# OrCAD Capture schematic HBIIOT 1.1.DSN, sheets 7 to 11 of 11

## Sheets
7 EXP CN: size C; title: BOOT, EXP; rev: 2.4.0
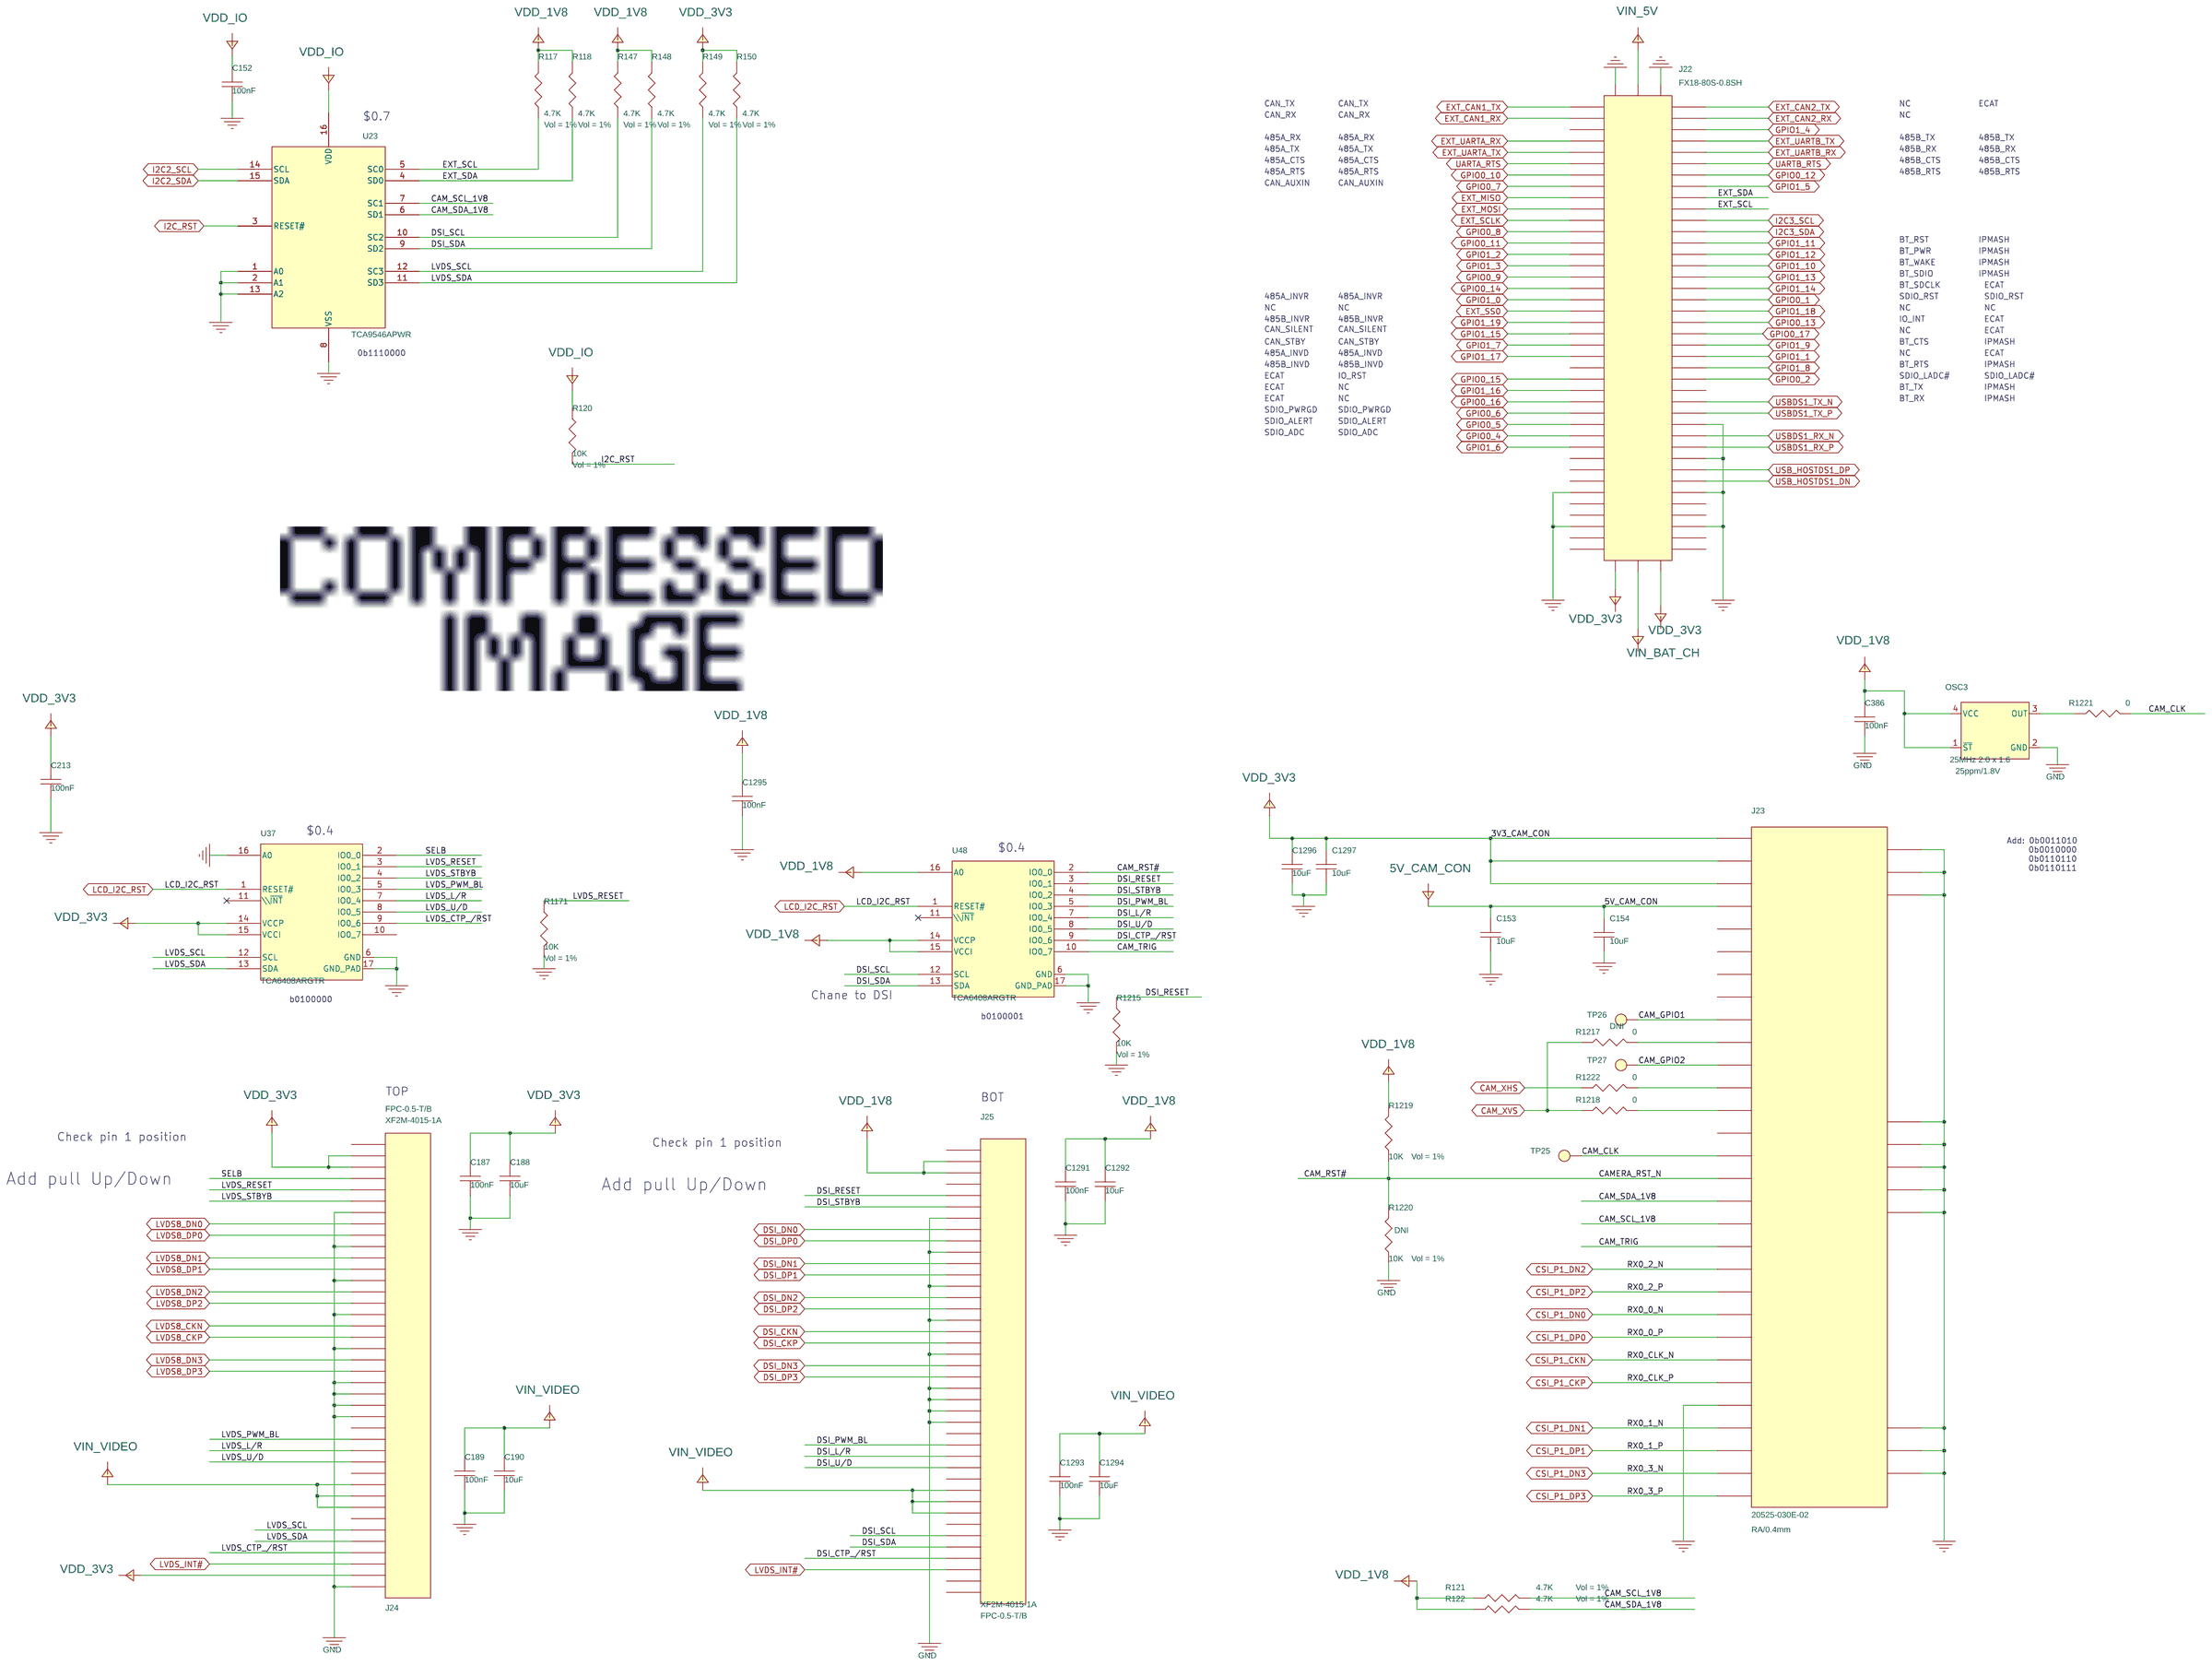
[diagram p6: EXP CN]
8 06 Sensors: size B
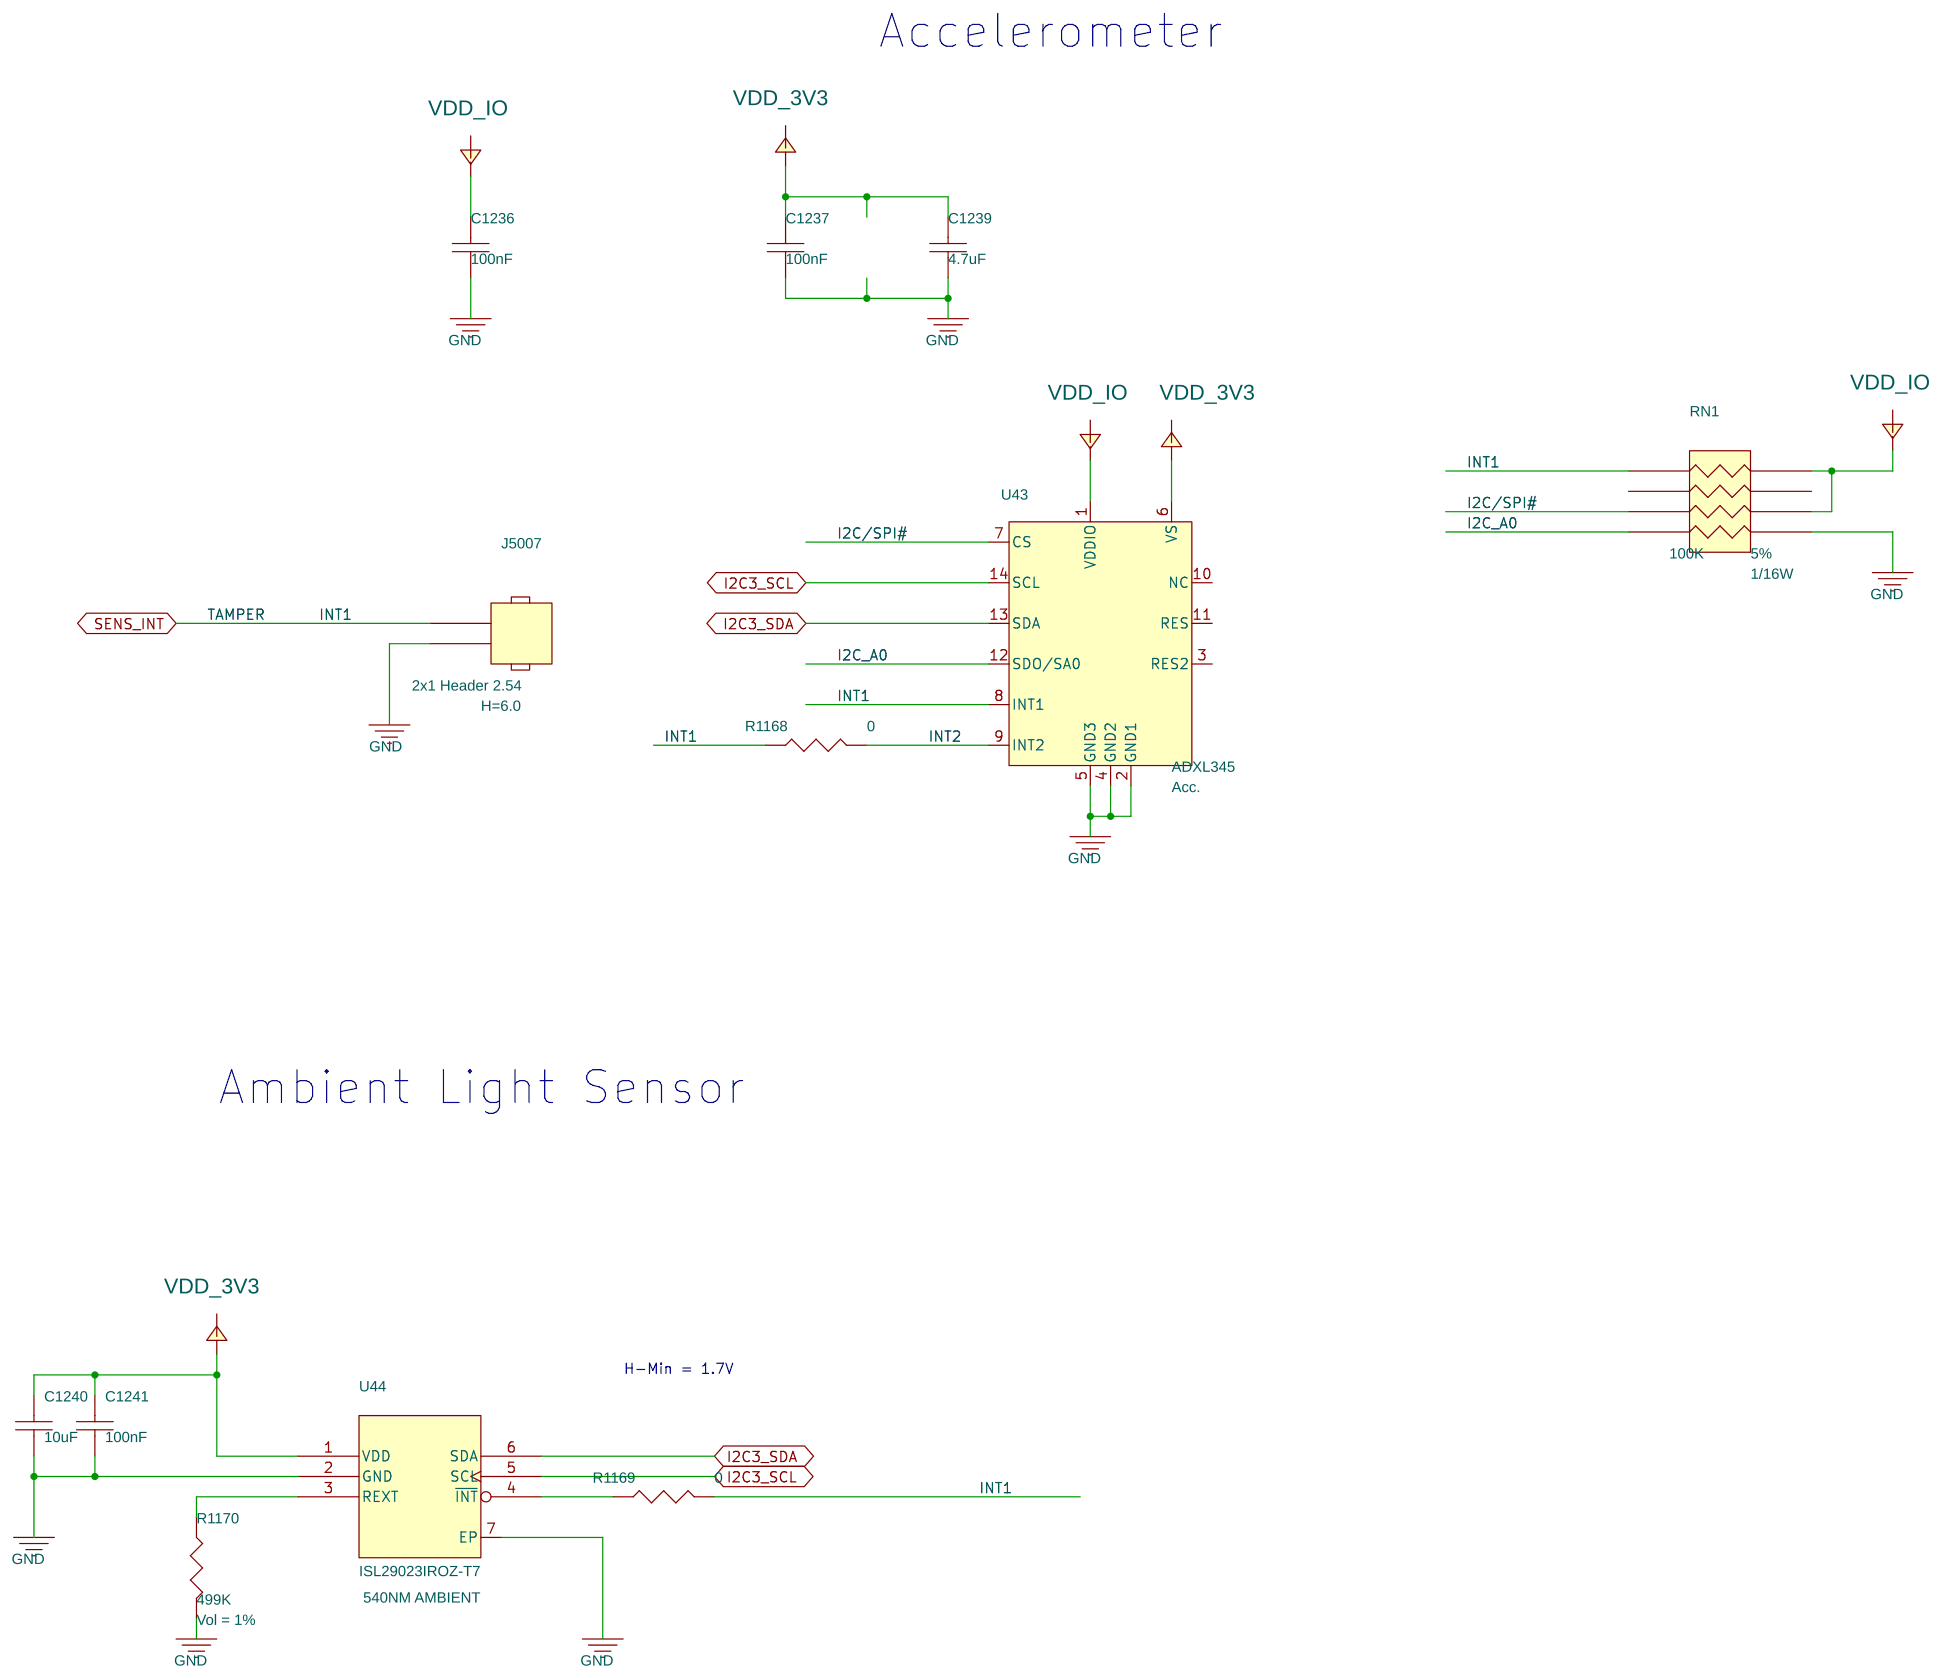
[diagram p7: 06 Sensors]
9 03 Battery Charger: size B; rev: 1.3
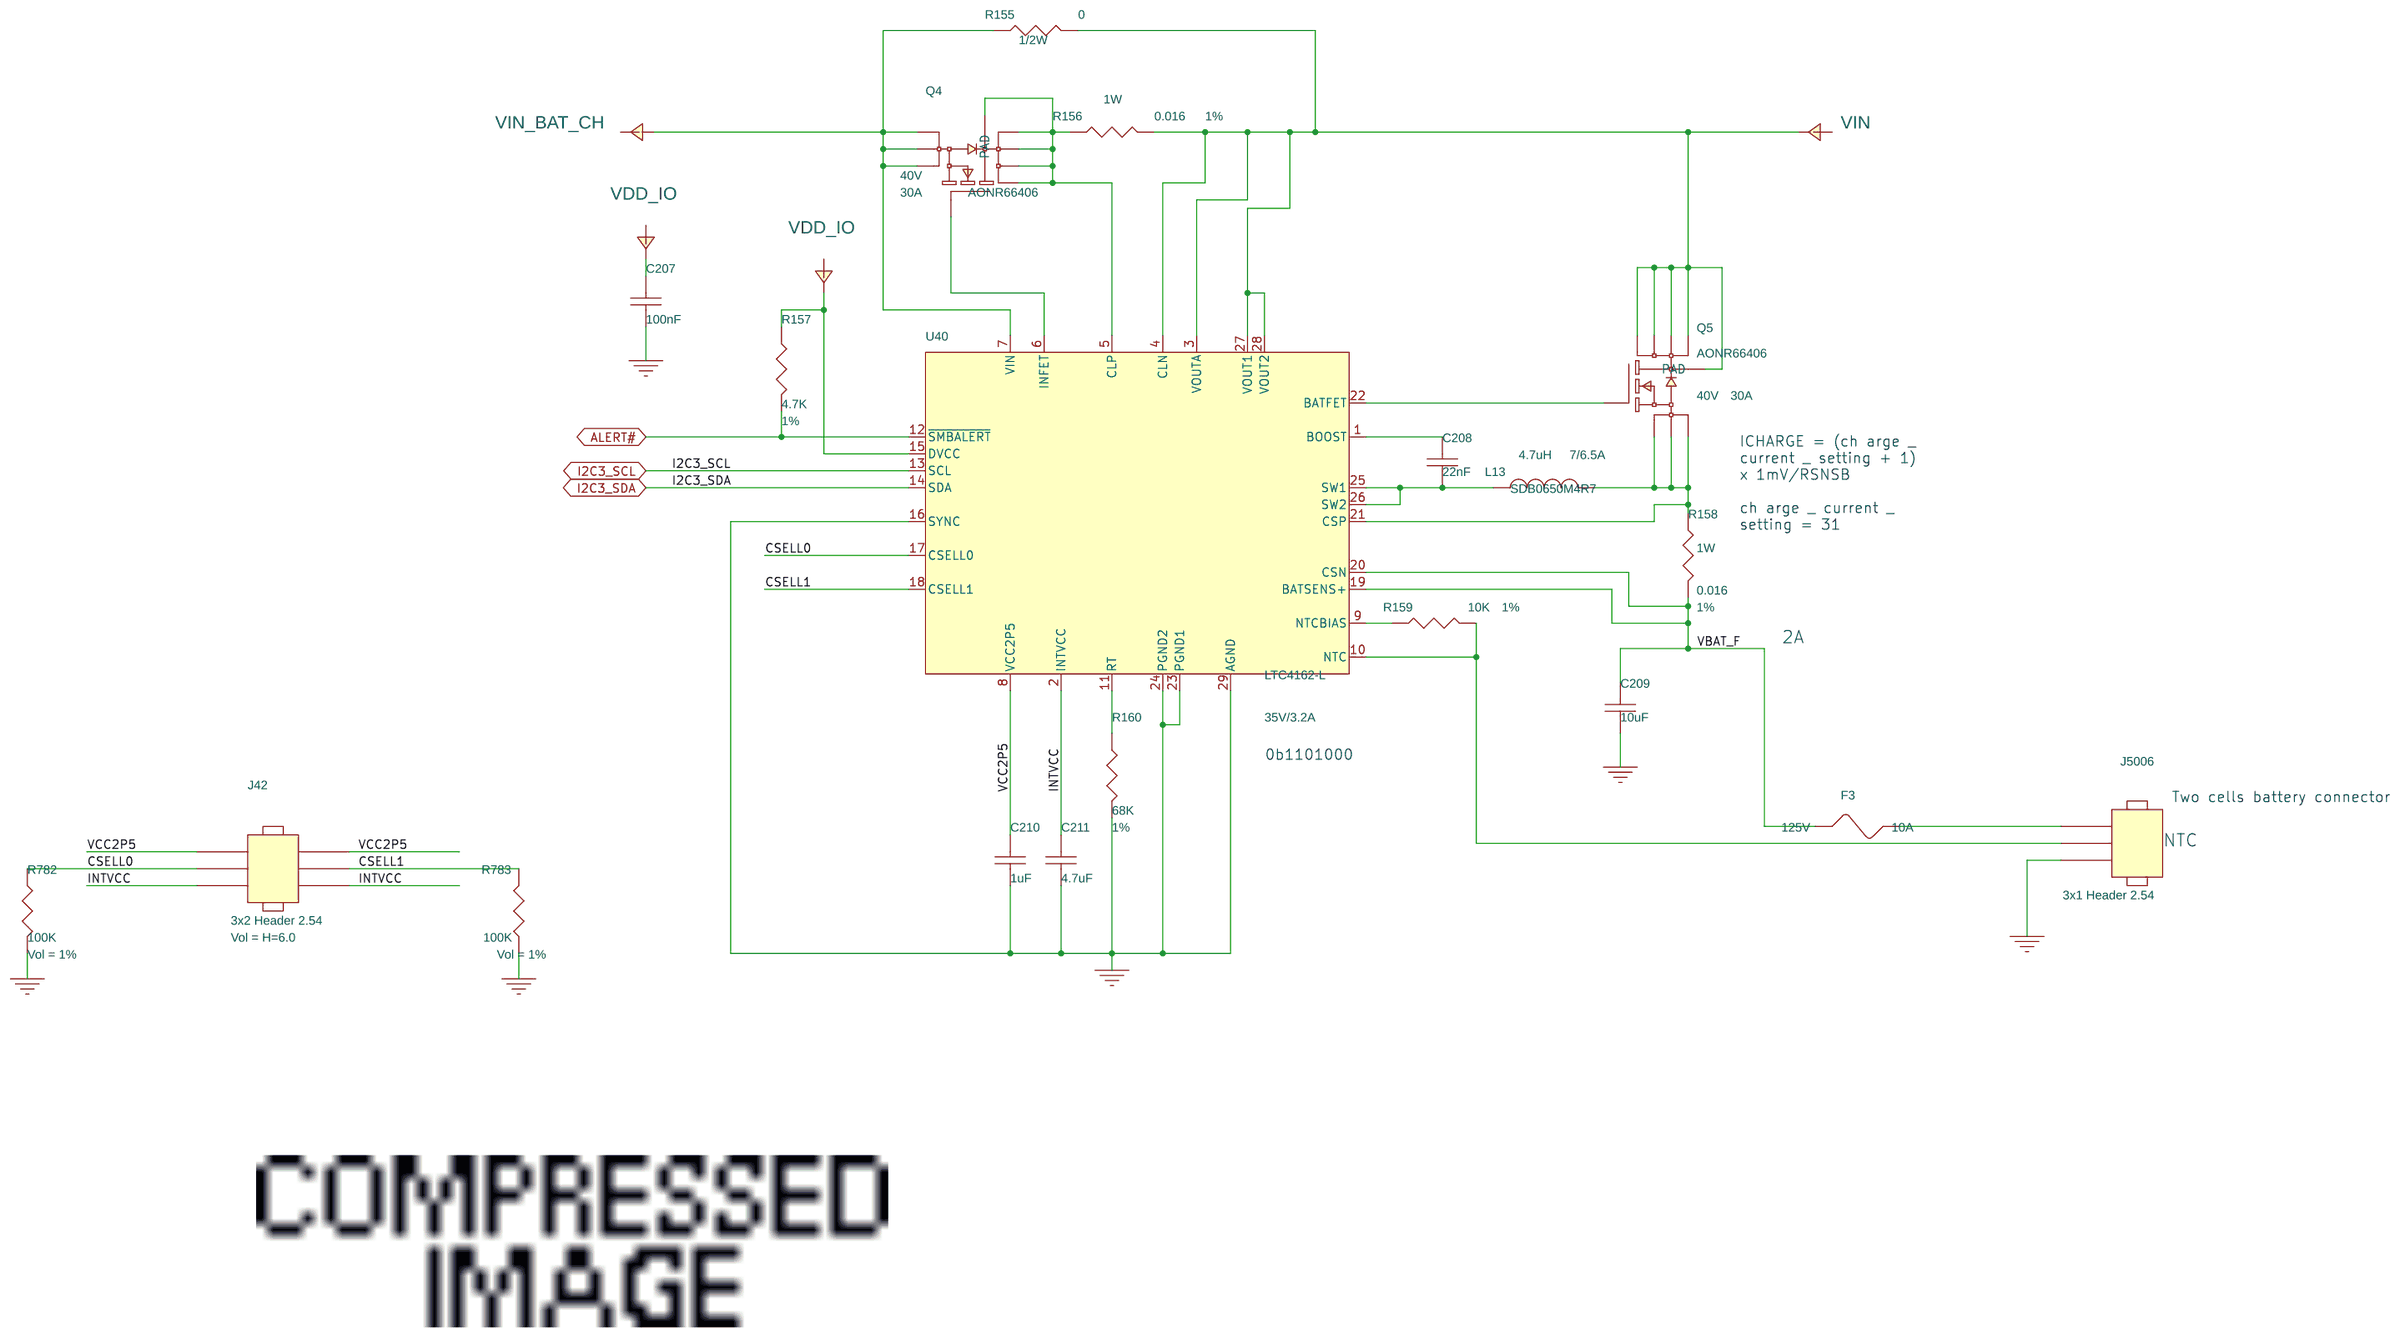
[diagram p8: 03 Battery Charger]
10 History: title: HISTORY
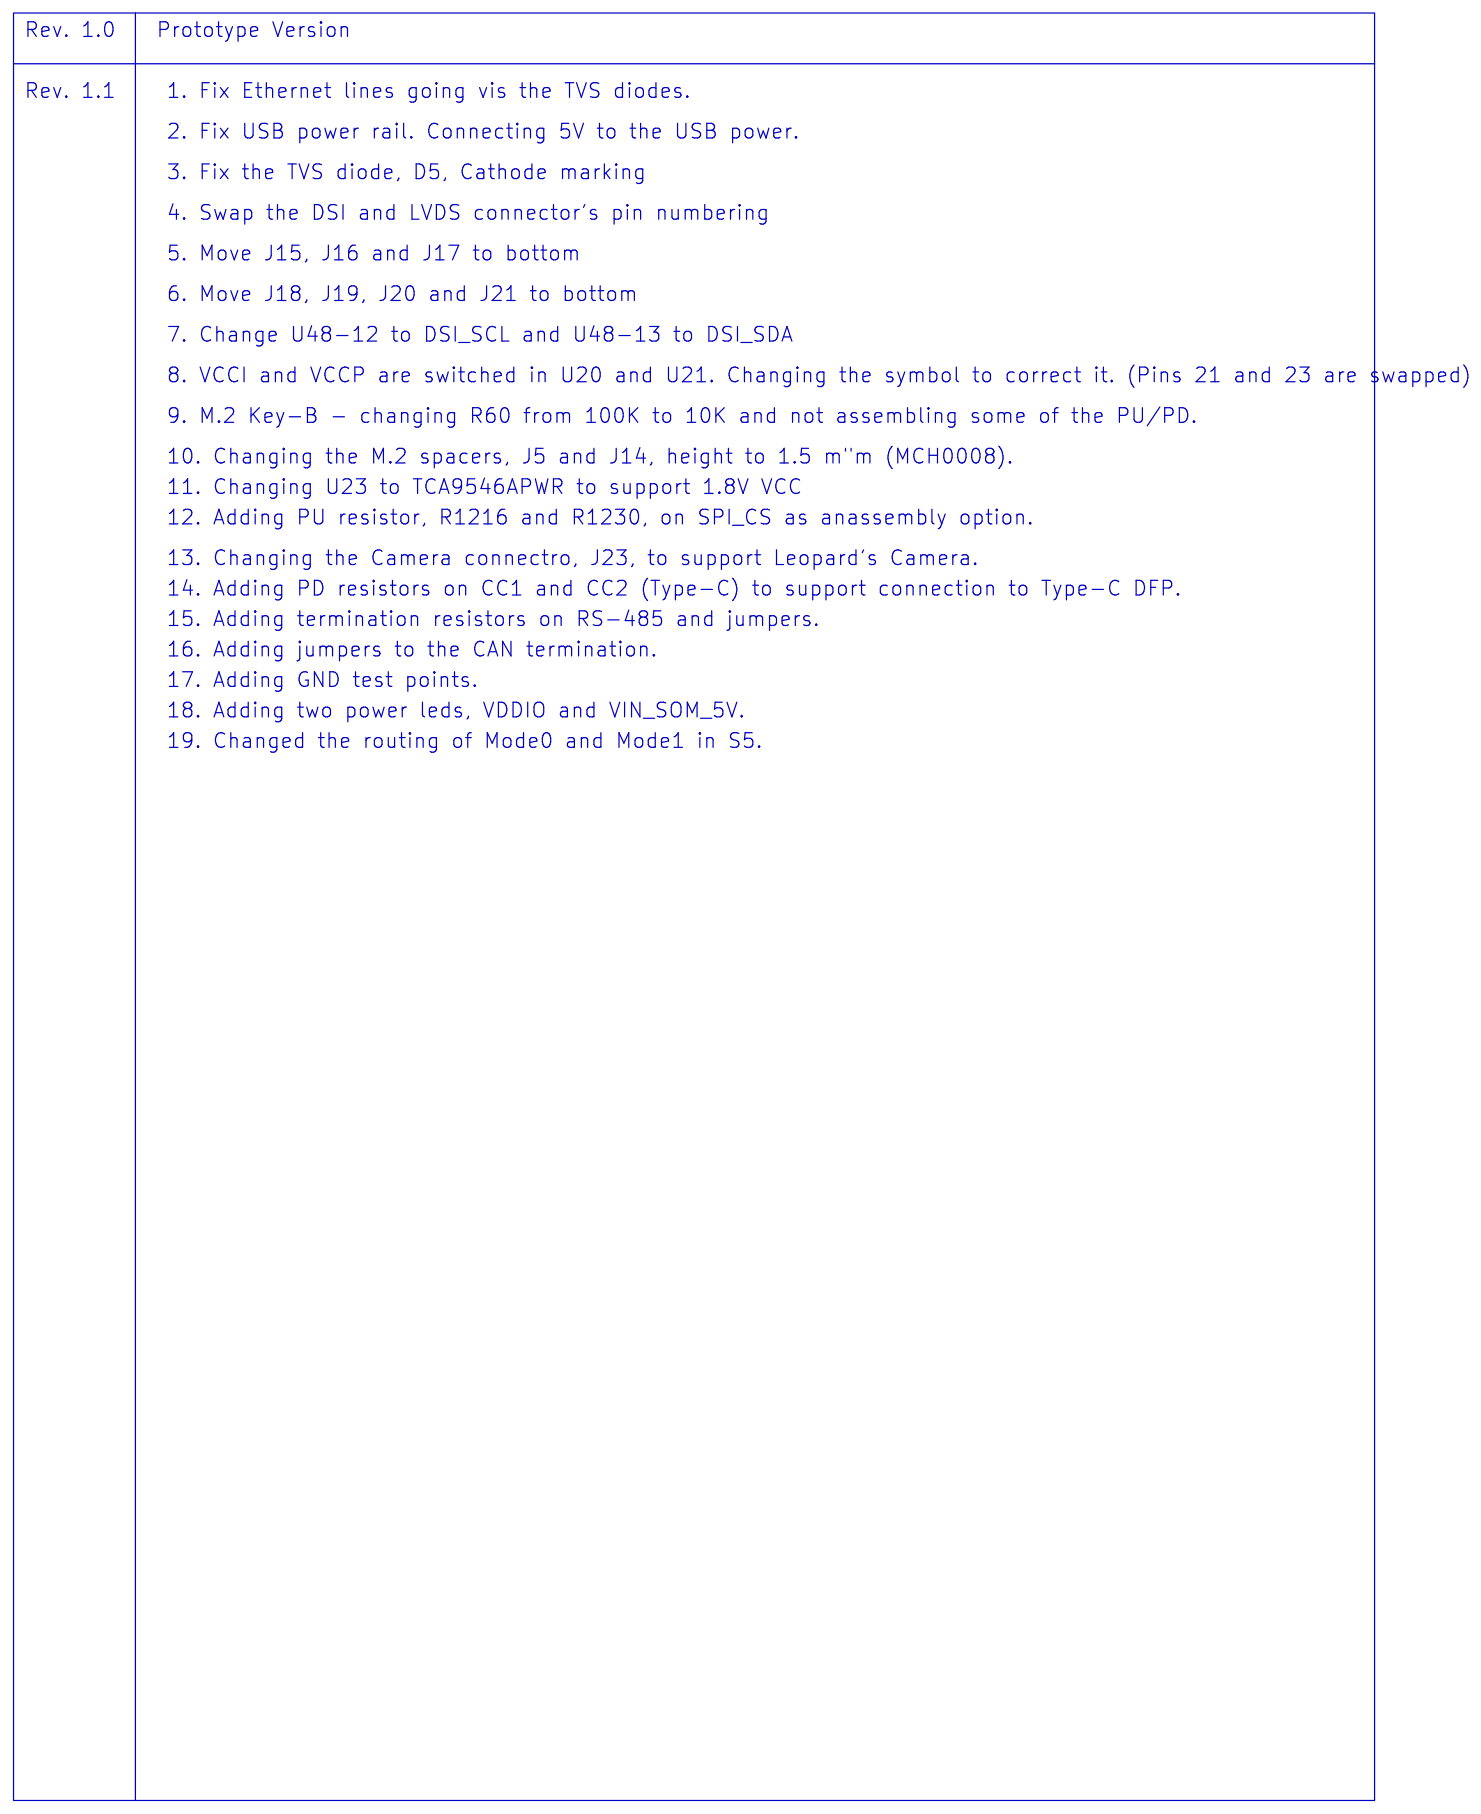
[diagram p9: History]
11 10 RS422/85/232: size C; title: RS422; rev: 1.0
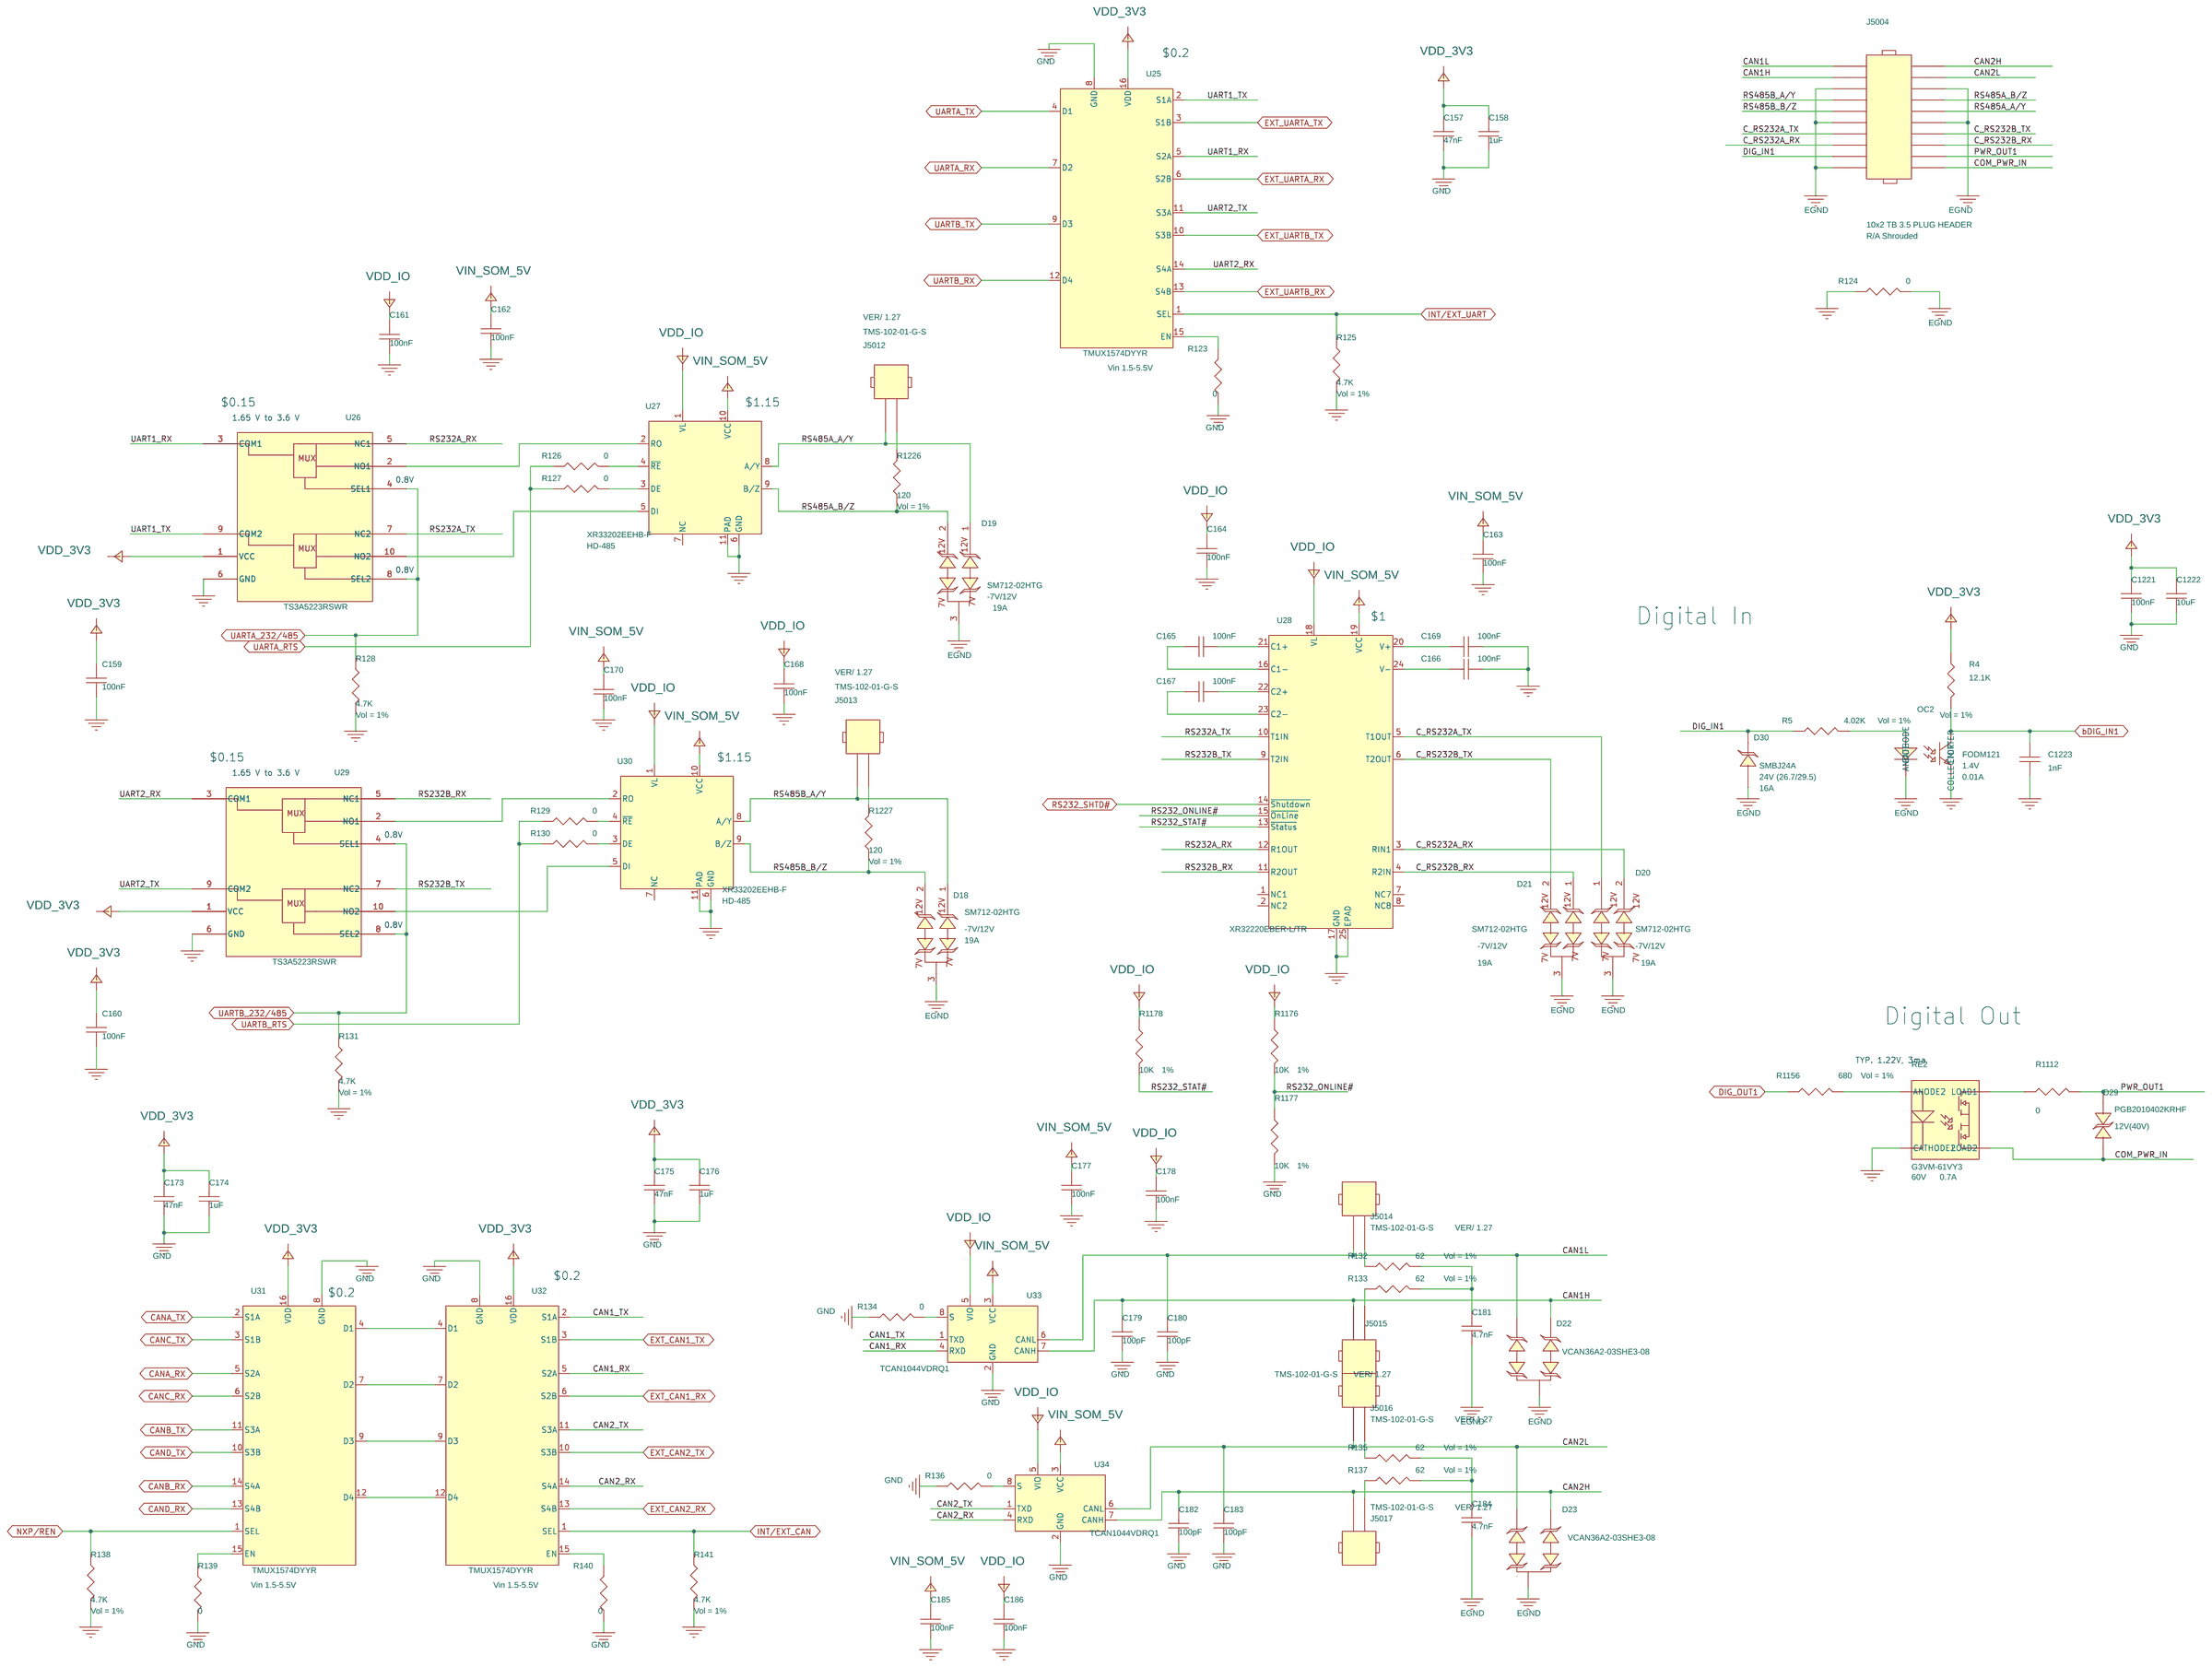
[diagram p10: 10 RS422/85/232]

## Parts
sheet 03 Battery Charger
C207  100nF  [C0402]
C208  22nF  [C0402]
C209  10uF  [C0603]
C210  1uF  [C0402]
C211  4.7uF  [C0603]
F3  125V  [0154010.DR]
J42  3x2 Header 2.54  [CH81062V200]
J5006  3x1 Header 2.54  [CH31032V200-NH]
L13  SDB0650M4R7  [SDB0650M4R7]
Q4  AONR66406  [AONR66406]
Q5  AONR66406  [AONR66406]
R155  0  [R0603]
R156  0.016  [R2512]
R157  4.7K  [R0402]
R158  0.016  [R2512]
R159  10K  [R0402]
R160  68K  [R0402]
R782  100K  [R0402]
R783  100K  [R0402]
U40  LTC4162-L  [LTC4162EUFD-LAD#TRPBF]
sheet 06 Sensors
C1236  100nF  [C0402]
C1237  100nF  [C0402]
C1239  4.7uF  [C0402]
C1240  10uF  [C0603]
C1241  100nF  [C0402]
J5007  2x1 Header 2.54  [CH31022V200-NH]
R1168  0  [R0402]
R1169  0  [R0402]
R1170  499K  [R0402]
RN1  100K  [RN0804]
U43  ADXL345  [ADXL345BCCZ-RL]
U44  ISL29023IROZ-T7  [ISL29023IROZ-T7]
sheet 10 RS422/85/232
C157  47nF  [C0402]
C158  1uF  [C0402]
C159  100nF  [C0402]
C160  100nF  [C0402]
C161  100nF  [C0402]
C162  100nF  [C0402]
C163  100nF  [C0402]
C164  100nF  [C0402]
C165  100nF  [C0402]
C166  100nF  [C0402]
C167  100nF  [C0402]
C168  100nF  [C0402]
C169  100nF  [C0402]
C170  100nF  [C0402]
C173  47nF  [C0402]
C174  1uF  [C0402]
C175  47nF  [C0402]
C176  1uF  [C0402]
C177  100nF  [C0402]
C178  100nF  [C0402]
C179  100pF  [C0402]
C180  100pF  [C0402]
C181  4.7nF  [C0402]
C182  100pF  [C0402]
C183  100pF  [C0402]
C184  4.7nF  [C0402]
C185  100nF  [C0402]
C186  100nF  [C0402]
C1221  100nF  [C0402]
C1222  10uF  [C0603]
C1223  1nF  [C0402]
D18  SM712-02HTG  [SM712-02HTG]
D19  SM712-02HTG  [SM712-02HTG]
D20  SM712-02HTG  [SM712-02HTG]
D21  SM712-02HTG  [SM712-02HTG]
D22  VCAN36A2-03SHE3-08  [VCAN36A2-03SHE3-08]
D23  VCAN36A2-03SHE3-08  [VCAN36A2-03SHE3-08]
D29  PGB2010402KRHF  [PGB2010402KRHF]
D30  SMBJ24A  [SMBJ24A]
J5004  10x2 TB 3.5 PLUG HEADER  [1787098]
J5012  TMS-102-01-G-S  [TMS-102-01-G-S]
J5013  TMS-102-01-G-S  [TMS-102-01-G-S]
J5014  TMS-102-01-G-S  [TMS-102-01-G-S]
J5015  TMS-102-01-G-S  [TMS-102-01-G-S]
J5016  TMS-102-01-G-S  [TMS-102-01-G-S]
J5017  TMS-102-01-G-S  [TMS-102-01-G-S]
OC2  FODM121  [FODM121]
R4  12.1K  [R0402]
R5  4.02K  [R0603]
R123  0  [R0402]
R124  0  [R0603]
R125  4.7K  [R0402]
R126  0  [R0402]
R127  0  [R0402]
R128  4.7K  [R0402]
R129  0  [R0402]
R130  0  [R0402]
R131  4.7K  [R0402]
R132  62  [R0603]
R133  62  [R0603]
R134  0  [R0402]
R135  62  [R0603]
R136  0  [R0402]
R137  62  [R0603]
R138  4.7K  [R0402]
R139  0  [R0402]
R140  0  [R0402]
R141  4.7K  [R0402]
R1112  0  [R0603]
R1156  680  [R0402]
R1176  10K  [R0402]
R1177  10K  [R0402]
R1178  10K  [R0402]
R1226  120  [R0402]
R1227  120  [R0402]
RE2  G3VM-61VY3  [G3VM-61VY3(TR05)]
U25  TMUX1574DYYR  [TMUX1574DYYR]
U26  TS3A5223RSWR  [TS3A5223RSWR]
U27  XR33202EEHB-F  [XR33202EEHB-F]
U28  XR32220EBER-L/TR  [XR32220EBER-L/TR]
U29  TS3A5223RSWR  [TS3A5223RSWR]
U30  XR33202EEHB-F  [XR33202EEHB-F]
U31  TMUX1574DYYR  [TMUX1574DYYR]
U32  TMUX1574DYYR  [TMUX1574DYYR]
U33  TCAN1044VDRQ1  [TCAN1044VDRQ1]
U34  TCAN1044VDRQ1  [TCAN1044VDRQ1]
sheet EXP CN
C152  100nF  [C0402]
C153  10uF  [C0402]
C154  10uF  [C0402]
C187  100nF  [C0402]
C188  10uF  [C0603]
C189  100nF  [C0402]
C190  10uF  [C0603]
C213  100nF  [C0402]
C386  100nF  [C0201]
C1291  100nF  [C0402]
C1292  10uF  [C0603]
C1293  100nF  [C0402]
C1294  10uF  [C0603]
C1295  100nF  [C0402]
C1296  10uF  [C0402]
C1297  10uF  [C0402]
J22  FX18-80S-0.8SH  [FX18-80S-0.8SH]
J23  20525-030E-02  [20525-030E-02]
J24  XF2M-4015-1A  [XF2M-4015-1A]
J25  XF2M-4015-1A  [XF2M-4015-1A]
OSC3  25MHz 2.0 x 1.6  [SIT1602BI-72-18E-25.000000]
R117  4.7K  [R0402]
R118  4.7K  [R0402]
R120  10K  [R0402]
R121  4.7K  [R0402]
R122  4.7K  [R0402]
R147  4.7K  [R0402]
R148  4.7K  [R0402]
R149  4.7K  [R0402]
R150  4.7K  [R0402]
R1171  10K  [R0402]
R1215  10K  [R0402]
R1217  0  [R0201]
R1218  0  [R0201]
R1219  10K  [R0402]
R1220  10K  [R0402]
R1221  0  [R0201]
R1222  0  [R0201]
TP25  R 20
TP26  R 20
TP27  R 20
U23  TCA9546APWR  [TCA9546APWR]
U37  TCA6408ARGTR  [TCA6408ARGTR]
U48  TCA6408ARGTR  [TCA6408ARGTR]

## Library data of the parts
C207 = CAP_NP1: CAP CER 0.1uF ±10% 10V X7R 0402; Category: Capacitors (Size: 0402); Digikey P/N: 1276-1002-2-ND; Manufacturer: Samsung Electro-Mechanics; Part Num#: CL05B104KP5NNNC; Rating: 10V; SolidRun P/N: CA20001; Vol: 10%
C208 = CAP_NP1: CAP CER 0.022UF 25V X7R 0402; Category: Capacitors (Size: 0402); Digikey P/N: 1276-1537-2-ND; Manufacturer: Samsung Electro-Mechanics; Part Num#: CL05B223KA5NNNC; Rating: 25V; SolidRun P/N: CA20822; Vol: 10%
C209 = CAP_NP1: CAP CER 10uF ±10% 16V X5R 0603; Digikey P/N: 490-10728-2-ND; Manufacturer: Murata Electronics North America; Part Num#: GRM188R61C106KAALD; Rating: 16V; SolidRun P/N: CA30014; Vol: 10%
C210 = CAP_NP1: CAP CER 1UF 10V X5R 0402; Category: Capacitors (Size: 0402); Digikey P/N: 1276-1076-1-ND; Manufacturer: Samsung Electro-Mechanics; Part Num#: CL05A105KP5NNNC; Rating: 10V; SolidRun P/N: CA20005; Vol: 10%
C211 = CAP_NP1: CAP CER 4.7uF ±10% 10V X5R 0603; Category: Capacitors (Size: 0603); Digikey P/N: 311-1455-1-ND; Manufacturer: YAGEO; Part Num#: CC0603KRX5R6BB475; Rating: 10V; SolidRun P/N: CA30017; Vol: 10%
F3 = FUSE1: FUSE BRD MNT 10A 125VAC/VDC SMD; Category: Fuse; Digikey P/N: F1251TR-ND; Manufacturer: Littelfuse Inc.; Rating: 10A; SolidRun P/N: FS00024; Datasheet: http://www.littelfuse.com/~/media/electronics/datasheets/fuses/littelfuse_fuse_154_154t_154l_154tl_datasheet.pdf.pdf
J42 = J-HEADER-3x2: 100 mil head 3 x 2 2.54mm H=6.0; Manufacturer: cvilux; SolidRun P/N: CO00507; Vol: H=6.0; Datasheet: https://www.cvilux.com/uploads/catalog/p285%20CH81-1.pdf
J5006 = J-HEADER-3x1: CH31 Series 2.54mm(.100") Single Row Pin Headers- 3 x 1 V TH; Category: CON-HEADER; Manufacturer: cvilux; SolidRun P/N: CO00509; VOL: H=6.0; Datasheet: https://www.cvilux.com/uploads/catalog/p283%20CH31.pdf
L13 = INDUCTOR1: IND 4.7uH 6.8 x 7.6 x 5 30.3mOhm 7/6.5A; Category: COILS-IND; Manufacturer: VIKING; Rating: 7/6.5A; SolidRun P/N: IN00045; Vol: 4.7uH; Datasheet: https://www.viking.com.tw/Templates/att/SDB_REV_B5-160912.pdf?lng=en
Q4 Q5 = MOSFET_N_DFN: 40V N-Channel AlphaSGT 30A; Category: TR-MOSFET-N; Digikey P/N: AONR66406-ND; Manufacturer: Alpha & Omega Semiconductor Inc; Rating: 30A; SolidRun P/N: TR00018; Vol: 40V; Datasheet: http://aosmd.com/res/data_sheets/AONR66406.pdf
R155 = RES1: RES SMD 0 OHM JUMPER 1/2W 0603; Category: Resistors (Size: 0603); Digikey P/N: 36-5110CT-ND; Manufacturer: Keystone Electronics; Part Num#: 5110; Rating: 1/2W; SolidRun P/N: RE30017
R156 R158 = RES1: 16 mOhms ±1% 1W Chip Resistor 2512 (6432 Metric) Current Sense Metal Element; Category: Resistors (Size: 2512); Digikey P/N: P16MTR-ND; Manufacturer: Panasonic Electronic Components; Part Num#: ERJ-M1WSF16MU; Rating: 1W; SolidRun P/N: RE70006; Vol: 1%
R117 R118 R121 R122 R147-R150 R157 = RES1: RES SMD 4.7K OHM 1% 1/16W 0402; Category: Resistors (Size: 0402); Digikey P/N: 311-4.7KLRCT-ND; Manufacturer: YAGEO; Part Num#: RC0402FR-074K7L; Rating: 1/16W; SolidRun P/N: RE20497; Vol: 1%
R159 = RES1: RES SMD 10K OHM 1% 1/16W 0402; Category: Resistors (Size: 0402); Digikey P/N: 311-10.0KLRCT-ND; Manufacturer: YAGEO; Part Num#: RC0402FR-0710KL; Rating: 1/16W; SolidRun P/N: RE20013; Vol: 1%
R160 = RES1: RES SMD 68K OHM 1% 1/16W 0402; Category: Resistors (Size: 0402); Digikey P/N: 311-68.0KLRCT-ND; Manufacturer: YAGEO; Part Num#: RC0402FR-0768KL; Rating: 1/16W; SolidRun P/N: RE20104; Vol: 1%
R782 R783 = RES1: RES SMD 100K OHM 1% 1/16W 0402; Digikey P/N: 311-100KLRCT-ND; Manufacturer: YAGEO; Part Num#: RC0402FR-07100KL; Rating: 1/16W; SolidRun P/N: RE20482; Vol: 1%
U40 = IC-LTC4162-x: Battery Charger 35V/3.2A MULTI-CELL LITHIUM-ION; Category: IC-PWR-BAT; Digikey P/N: LTC4162EUFD-LAD#TRPBF-ND; Manufacturer: Linear Technology/Analog Devices; Rating: 35V/3.2A; SolidRun P/N: IC01252; VOL: Li-Ion; Datasheet: http://www.analog.com/media/en/technical-documentation/data-sheets/LTC4162-L.pdf
C161-C170 C177 C178 C185 C186 C1236 C1237 C1241 = CAP_NP1: CAP CER 0.1uF ±10% 10V X7R 0402; Digikey P/N: 1276-1002-2-ND; Manufacturer: Samsung Electro-Mechanics; Part Num#: CL05B104KP5NNNC; Rating: 10V; SolidRun P/N: CA20001; Vol: 10%
C1239 = CAP_NP1: CAP CER 4.7uF ±20% 6.3V X5R 0402; Digikey P/N: 490-5408-1-ND; Manufacturer: Murata Electronics North America; Part Num#: GRM155R60J475ME87D; Rating: 6.3V; SolidRun P/N: CA20800; Vol: 20%
C1240 = CAP_NP1: CAP CER 10uF ±10% 6.3V X5R 0603; Digikey P/N: 1276-1038-1-ND; Manufacturer: Samsung Electro-Mechanics; Part Num#: CL10A106KQ8NNNC; Rating: 6.3V; SolidRun P/N: CA30001; Vol: 10%
J5007 = J-HEADER_2x1: Two pin header - CH31022V200-NH; Manufacturer: CVILUX; SolidRun P/N: CO00049; Vol: H=6.0; Datasheet: https://www.cvilux.com/uploads/catalog/p283%20CH31.pdf
R123 R126 R127 R129 R130 R134 R136 R139 R140 R1168 R1169 = RES1: RES SMD 0 OHM JUMPER 1/16W 0402; Digikey P/N: 311-0.0JRCT-ND; Manufacturer: YAGEO; Part Num#: RC0402JR-070RL; Rating: 1/16W; SolidRun P/N: RE20009
R1170 = RES1: RES SMD 499K OHM 1% 1/16W 0402; Category: Resistors (Size: 0402); Digikey P/N: 311-499KLRTR-ND; Manufacturer: YAGEO; Part Num#: RC0402FR-07499KL; Rating: 1/16W; SolidRun P/N: RE20519; Vol: 1%
RN1 = RES-4: Resistor Network 4-RES 100K Ohm 5% 1/16W 0804; Digikey P/N: YC124J-100KCT-ND; Manufacturer: YAGEO; Part Num#: YC124-JR-07100KL; Rating: 1/16W; SolidRun P/N: RN00037; Vol: 5%
U43 = IC-ADX345: Accelerometer X, Y, Z Axis ±2g, 4g, 8g, 16g 0.05Hz ~ 1.6kHz 14-LGA (3x5); Digikey P/N: ADXL345BCCZ-RLTR-ND; Manufacturer: Analog Devices Inc.; SolidRun P/N: IC01454; Vol: Acc.; Datasheet: https://www.analog.com/media/en/technical-documentation/data-sheets/ADXL345.pdf
U44 = IC-ISL29023: SENSOR OPT 540NM AMBIENT 6ODFN; Digikey P/N: ISL29023IROZ-T7DKR-ND; Manufacturer: Renesas Electronics America Inc; SolidRun P/N: IC01550; Vol: 540NM AMBIENT; Datasheet: https://media.digikey.com/pdf/Data%20Sheets/Renesas/isl29023_DS.pdf
C157 C173 C175 = CAP_NP1: CHIP CAP 47nF 6.3V 0402 X7R; Manufacturer: Samsung Electro-Mechanics; Part Num#: CL05B473MQQNNNE; Rating: 6.3V; SolidRun P/N: CA20012; Vol: 10%
C158 C174 C176 = CAP_NP1: CAP CER 1uF ±10% 6.3V X7R 0402; Digikey P/N: 1276-1513-1-ND; Manufacturer: Samsung Electro-Mechanics; Part Num#: CL05B105KQ5NQNC; Rating: 6.3V; SolidRun P/N: CA20132; Vol: 10%
C159 C160 = CAP_NP1: CAP CER 0.1uF ±10% 16V X7R 0402; Digikey P/N: 1276-1001-1-ND; Manufacturer: Samsung Electro-Mechanics; Part Num#: CL05B104KO5NNNC; Rating: 16V; SolidRun P/N: CA20013; Vol: 10%
C179 C180 C182 C183 = CAP_NP1: CAP CER 100pF ±5% 50V C0G/NP0 0402; Digikey P/N: CL05C101JB5NNND-ND; Manufacturer: Samsung Electro-Mechanics; Part Num#: CL05C101JB5NNND; Rating: 50V; SolidRun P/N: CA20120; Vol: 5%
C181 C184 = CAP_NP1: CAP CER 4.7nF ±10% 25V X7R 0402; Category: Capacitors (Size: 0402); Digikey P/N: 1276-1571-1-ND; Manufacturer: Samsung Electro-Mechanics; Part Num#: CL05B472KA5NNNC; Rating: 25V; SolidRun P/N: CA20802; Vol: 10%
C152 C187 C189 C213 C1221 C1291 C1293 C1295 = CAP_NP1: CAP CER 0.1uF ±10% 16V X7R 0402; Category: Capacitors (Size: 0402); Digikey P/N: 1276-1001-1-ND; Manufacturer: Samsung Electro-Mechanics; Part Num#: CL05B104KO5NNNC; Rating: 16V; SolidRun P/N: CA20013; Vol: 10%
C188 C190 C1222 C1292 C1294 = CAP_NP1: CAP CER 10uF ±10% 16V X5R 0603; Category: Capacitors (Size: 0603); Digikey P/N: 490-10728-2-ND; Manufacturer: Murata Electronics North America; Part Num#: GRM188R61C106KAALD; Rating: 16V; SolidRun P/N: CA30014; Vol: 10%
C1223 = CAP_NP1: CAP CER 1000pF ±10% 50V X7R 0402; Digikey P/N: 1276-1032-1-ND; Manufacturer: Samsung Electro-Mechanics; Part Num#: CL05B102KB5NNNC; Rating: 50V; SolidRun P/N: CA20008; Vol: 10%
D18-D21 = TVS-SM712-RS485: SM712 Series 600W Asymmetrical TVS Diode Array For RS-485; Digikey P/N: F6450TR-ND; Manufacturer: Littelfuse Inc.; Rating: 19A; SolidRun P/N: DI00265; Vol: -7V/12V; Datasheet: http://www.littelfuse.com/~/media/electronics/datasheets/tvs_diode_arrays/littelfuse_tvs_diode_array_sm712_datasheet.pdf.pdf
D22 D23 = D-ESDCAN05-TVS: 63V Clamp 2.4A (8/20µs) Ipp Tvs Diode Surface Mount SOT-23-3; Digikey P/N: 112-VCAN36A2-03SHE3-08TR-ND; Manufacturer: Vishay General Semiconductor - Diodes Division; Rating: 3A; SolidRun P/N: DI00314; Vol: 39/61V; Datasheet: https://www.vishay.com/docs/86182/vcan36a2-03s.pdf
D29 = TVS-BI: 40V (Typ) Clamp - Ipp Tvs Diode Surface Mount 0402; Digikey P/N: F3268TR-ND; Manufacturer: Littelfuse Inc.; SolidRun P/N: DI00305; Vol: 12V(40V); Datasheet: https://www.littelfuse.com/media?resourcetype=datasheets&itemid=1cf7e392-caf0-4fab-b036-960455903eff&filename=littelfuse-pulseguard-pgb2-0402-datasheet
D30 = TVS-UNI-OLD: TVS Diodes - TVS DIODE 24V 38.9V DO214AA; Digikey P/N: SMBJ24AR5GTR-ND; Manufacturer: Taiwan Semiconductor Corporation; Rating: 16A; SolidRun P/N: DI00218; Vol: 24V (26.7/29.5); Datasheet: http://www.taiwansemi.com/products/datasheet/SMBJ%20SERIES_O1701.pdf
J5004 = J-HEADER_10x2: 20 Position Terminal Block Header, Male Pins, Shrouded (4 Side) 0.138" (3.50mm) 90°, Right Angle Through Hole; Digikey P/N: 277-8743-ND; Manufacturer: Phoenix Contact; SolidRun P/N: CO00961; Vol: R/A Shrouded; Datasheet: https://mm.digikey.com/Volume0/opasdata/d220001/medias/docus/572/1787098.pdf
J5012-J5017 = J-HEADER_2x1: Connector Header Through Hole 2 position 0.050" (1.27mm); Digikey P/N: SAM12199-ND; Manufacturer: Samtec Inc.; Rating: H=5.84; SolidRun P/N: CO00974; Vol: VER/ 1.27; Datasheet: https://mm.digikey.com/Volume0/opasdata/d220001/medias/docus/6129/tms-1xx-xx-xx-x-xx-xxx-mkt.pdf
OC2 = OPTC-DC-4P: Optoisolator Transistor Output 3750Vrms 1 Channel 4-Mini-Flat; Digikey P/N: FODM121-ND; Manufacturer: ON Semiconductor; Rating: 0.01A; SolidRun P/N: IC01209; Vol: 1.4V; Datasheet: https://www.fairchildsemi.com/datasheets/FO/FODM121.pdf
R4 = RES1: RES SMD 12.1K OHM 1% 1/16W 0402; Digikey P/N: 311-12.1KLRCT-ND; Manufacturer: YAGEO; Part Num#: RC0402FR-0712K1L; Rating: 1/16W; SolidRun P/N: RE20433; Vol: 1%
R5 = RES1: RES SMD 4.02K OHM 1% 1/10W 0603; Digikey P/N: YAG5341TR-ND; Manufacturer: YAGEO; Part Num#: AC0603FR-074K02L; Rating: 1/10W; SolidRun P/N: RE30019; Vol: 1%
R124 = RES1: RES SMD 0 OHM JUMPER 1/2W 0603; Digikey P/N: 36-5110CT-ND; Manufacturer: Keystone Electronics; Part Num#: 5110; Rating: 1/2W; SolidRun P/N: RE30017
R125 R128 R131 R138 R141 = RES1: RES SMD 4.7K OHM 1% 1/16W 0402; Digikey P/N: 311-4.7KLRCT-ND; Manufacturer: YAGEO; Part Num#: RC0402FR-074K7L; Rating: 1/16W; SolidRun P/N: RE20497; Vol: 1%
R132 R133 R135 R137 = RES1: RES SMD 62 OHM 1% 1/4W 0603; Digikey P/N: RCS060362R0FKEA-ND; Manufacturer: Vishay Dale; Part Num#: RCS060362R0FKEA; Rating: 1/4W; SolidRun P/N: RE30025; Vol: 1%
R1112 = RES1: RES SMD 0 OHM JUMPER 1/10W 0603; Digikey P/N: 311-0.0GRCT-ND; Manufacturer: YAGEO; Part Num#: RC0603JR-070RL; Rating: 1/10W; SolidRun P/N: RE30006
R1156 = RES1: RES SMD 680 OHM 1% 1/16W 0402; Digikey P/N: 311-680LRCT-ND; Manufacturer: YAGEO; Part Num#: RC0402FR-07680RL; Rating: 1/16W; SolidRun P/N: RE20428; Vol: 1%
R1176-R1178 = RES1: RES SMD 10K OHM 1% 1/16W 0402; Category : Resistors (Size: 0402); Digikey P/N: 311-10.0KLRCT-ND; Manufacturer: YAGEO; Part Num#: RC0402FR-0710KL; Rating: 1/16W; SolidRun P/N: RE20013; Vol: 1%
R1226 R1227 = RES1: RES SMD 120 OHM 1% 1/16W 0402; Digikey P/N: 311-120LRCT-ND; Manufacturer: YAGEO; Part Num#: RC0402FR-07120RL; Rating: 1/16W; SolidRun P/N: RE20043; Vol: 1%
RE2 = RE-CPC1006N: SSR RELAY SPST-NO 700MA 0-60V; Digikey P/N: Z10318TR-ND; Manufacturer: Omron Electronics Inc-EMC Div; Rating: 0.7A; SolidRun P/N: IC01811; Vol: 60V; Datasheet: https://omronfs.omron.com/en_US/ecb/products/pdf/en-g3vm_61g_61vy1.pdf
U25 U31 U32 = IC-TMUX1574DYYR: 4 Circuit IC Switch 2:1 4.5Ohm 16-SOT-23-THIN; Digikey P/N: 296-TMUX1574DYYRTR-ND; Manufacturer: Texas Instruments; SolidRun P/N: IC01637; Vol: Vin 1.5-5.5V; Datasheet: https://www.ti.com/general/docs/suppproductinfo.tsp?distId=10&gotoUrl=https%3A%2F%2Fwww.ti.com%2Flit%2Fgpn%2Ftmux1574
U26 U29 = IC-TS3A5223RSWR: Dual analog switch - SPDT; Digikey P/N: 296-35687-2-ND; Manufacturer: Texas Instruments; SolidRun P/N: IC00220; Vol: SPDT; Datasheet: http://www.ti.com/lit/ds/symlink/ts3a5223.pdf
U27 U30 = IC-XR33202: 1/1 Transceiver Half RS422, RS485 10-DFN (3x3); Digikey P/N: 1016-2098-ND; Manufacturer: MaxLinear, Inc.; SolidRun P/N: IC01239; Vol: HD-485; Datasheet: https://www.exar.com/content/document.ashx?id=21713
U28 = IC-XR32220: 2/2 Transceiver Full RS232 24-QFN (4x4); Digikey P/N: 1016-XR32220EBER-L/TR-ND; Manufacturer: MaxLinear, Inc.; SolidRun P/N: IC01921; Datasheet: https://assets.maxlinear.com/web/documents/xr32220_ds_1e_080320.pdf
U33 U34 = IC-TCAN1044-SOIC8: 1/1 Transceiver - CAN 8-SOIC; Digikey P/N: 296-TCAN1044VDRQ1TR-ND; Manufacturer: Texas Instruments; SolidRun P/N: IC01667; Datasheet: https://www.ti.com/general/docs/suppproductinfo.tsp?distId=10&gotoUrl=https%3A%2F%2Fwww.ti.com%2Flit%2Fgpn%2Ftcan1044-q1
C153 C154 C1296 C1297 = CAP_NP1: CAP CER 10uF ±20% 6.3V X6S 0402; Digikey P/N: 490-13233-1-ND; Manufacturer: Murata Electronics North America; Part Num#: GRM155C80J106ME11D; Rating: 6.3V; SolidRun P/N: CA20131; Vol: 20%
C386 = CAP_NP1: CAP CER 0.1uF ±10% 10V X5R 0201; Digikey P/N: 587-2241-1-ND; Manufacturer: TAIYO YUDE; Part Num#: LMK063BJ104KP-F; Rating: 10V; SolidRun P/N: CA10004; Vol: 10%
J22 = J-FX18-80: 80 Position Connector Receptacle, Center Strip Contacts Surface Mount, Right Angle Gold; Digikey P/N: H12015-ND; Manufacturer: Hirose Electric Co Ltd; SolidRun P/N: CO00766; Vol: RCPT, R/A; Datasheet: https://www.hirose.com/product/document?clcode=CL0579-0005-3-00&productname=FX18-100P-0.8SH&series=FX18&documenttype=Catalog&lang=en&documentid=D31695_en
J23 = J-20525-030E-02C: 30 Position FPC Connector Contacts, Top 0.016" (0.40mm) Surface Mount, Right Angle; Digikey P/N: 3508-20525-030E-02TR-ND; Manufacturer: I-PEX; SolidRun P/N: CO00959; Vol: RA/0.4mm; Datasheet: https://www.i-pex.com/sites/default/files/downloads/pdf/CATALOG_CABLINE-CA_E.pdf
J24 J25 = J-FPC40: 40 Position FPC Connector Contacts, Top and Bottom 0.020" (0.50mm) Surface Mount, Right Angle; Digikey P/N: OR729TR-ND; Manufacturer: Omron Electronics Inc-EMC Div; SolidRun P/N: CO00681; Vol: FPC-0.5-T/B; Datasheet: https://media.digikey.com/pdf/Data%20Sheets/Omron%20PDFs/XF2M.pdf
OSC3 = OSC_4P_(3): 25 MHz XO (Standard) HCMOS, LVCMOS Oscillator 1.8V Enable/Disable 4-SMD, No Lead; Digikey P/N: 1473-SIT1602BI-72-18E-25.000000-ND; Manufacturer: SiTime; Rating: 25ppm/1.8V; SolidRun P/N: OC00059; Datasheet: https://www.sitime.com/datasheet/SiT1602
R120 R1171 R1215 R1219 = RES1: RES SMD 10K OHM 1% 1/16W 0402; Digikey P/N: 311-10.0KLRCT-ND; Manufacturer: YAGEO; Part Num#: RC0402FR-0710KL; Rating: 1/16W; SolidRun P/N: RE20013; Vol: 1%
R1217 = RES1: RES SMD 0 OHM JUMPER 1/20W 0201; ASSEMBLY: DNI; BOM_IGNORE: TRUE; Digikey P/N: RC0201JR-070RL; Manufacturer: YAGEO; Part Num#: RC0201JR-070RL; Rating: 1/20W; SolidRun P/N: RE10003
R1218 R1221 R1222 = RES1: RES SMD 0 OHM JUMPER 1/20W 0201; Digikey P/N: RC0201JR-070RL; Manufacturer: YAGEO; Part Num#: RC0201JR-070RL; Rating: 1/20W; SolidRun P/N: RE10003
R1220 = RES1: RES SMD 10K OHM 1% 1/16W 0402; ASSEMBLY: DNI; BOM_IGNORE: TRUE; Digikey P/N: 311-10.0KLRCT-ND; Manufacturer: YAGEO; Part Num#: RC0402FR-0710KL; Rating: 1/16W; SolidRun P/N: RE20013; Vol: 1%
TP25-TP27 = T_POINT_R: TEST POINT 20 mil - ultra miniature; ASSEMBLY: DNI; BOM_IGNORE: TRUE; Part Num#: N/A; SolidRun P/N: TP00003
U23 = IC-TCA9546APWR: IC BUS SWITCH 2 X 1:4 16TSSOP; Digikey P/N: 296-40578-2-ND; Manufacturer: Texas Instruments; SolidRun P/N: IC01984; Datasheet: https://www.ti.com/general/docs/suppproductinfo.tsp?distId=10&gotoUrl=https%3A%2F%2Fwww.ti.com%2Flit%2Fgpn%2Ftca9546a
U37 U48 = IC-TCA6408ARGTR: I/O Expander 8 I²C, SMBus 400kHz 16-QFN (3x3); Digikey P/N: 296-24825-2-ND; Manufacturer: Texas Instruments; SolidRun P/N: IC01238; Datasheet: http://www.ti.com/lit/ds/symlink/tca6408a.pdf

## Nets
GND: C152.2 C153.2 C154.2 C157.2 C158.2 C159.2 C160.2 C161.2 C162.2 C163.2 C164.2 C166.2 C168.2 C169.2 C170.2 C173.2 C174.2 C175.2 C176.2 C177.2 C178.2 C179.2 C180.2 C182.2 C183.2 C185.2 C186.2 C187.2 C188.2 C189.2 C190.2 C207.2 C209.2 C210.2 C211.2 C213.2 C386.2 C1221.2 C1222.2 C1223.2 C1236.2 C1237.2 C1239.2 C1240.2 C1241.2 C1291.2 C1292.2 C1293.2 C1294.2 C1295.2 C1296.2 C1297.2 J22.35 J22.38 J22.69 J22.72 J22.75 J22.78 J22.P1 J22.P3 J23.26 J23.31 J23.32 J23.33 J23.34 J23.35 J23.36 J23.37 J23.38 J23.39 J23.40 J23.41 J24.1 J24.16 J24.17 J24.18 J24.19 J24.22 J24.25 J24.28 J24.31 J24.34 J25.7 J25.10 J25.13 J25.16 J25.19 J25.22 J25.23 J25.24 J25.25 J5006.3 J5007.2 OC2.3(EMITTER) OSC3.2(GND) R123.2 R124.1 R125.2 R128.2 R131.2 R134.1 R136.1 R138.2 R139.2 R140.2 R141.2 R160.2 R782.2 R783.2 R1170.2 R1171.2 R1177.2 R1215.2 R1220.2 RE2.2(CATHODE2) RN1.5 U23.1(A0) U23.2(A1) U23.8(VSS) U23.13(A2) U25.8(GND) U26.6(GND) U27.6(GND) U27.11(PAD) U28.17(GND) U28.25(EPAD) U29.6(GND) U30.6(GND) U30.11(PAD) U31.8(GND) U32.8(GND) U33.2(GND) U34.2(GND) U37.6(GND) U37.16(A0) U37.17(GND_PAD) U40.16(SYNC) U40.23(PGND1) U40.24(PGND2) U40.29(AGND) U43.2(GND1) U43.4(GND2) U43.5(GND3) U44.2(GND) U44.7(EP) U48.6(GND) U48.17(GND_PAD) ; also on sheet 1 2 3 4 5 6
VBAT_F: C209.1 F3.1 R158.2 U40.19(BATSENS+) U40.20(CSN)
VCC2P5: C210.1 J42.1 J42.2 U40.8(VCC2P5)
VDD_1V8: C386.1 C1291.1 C1292.1 C1295.1 J25.2 J25.3 OSC3.1(~{ST}) OSC3.4(VCC) R117.2 R118.2 R121.1 R122.1 R147.2 R148.2 R1219.1 U48.14(VCCP) U48.15(VCCI) U48.16(A0) ; also on sheet 1 2
VDD_3V3: C157.1 C158.1 C159.1 C160.1 C173.1 C174.1 C175.1 C176.1 C187.1 C188.1 C213.1 C1221.1 C1222.1 C1237.1 C1239.1 C1240.1 C1241.1 C1296.1 C1297.1 J22.P4 J22.P6 J23.1 J23.2 J23.3 J24.2 J24.38 J24.39 R4.1 R149.2 R150.2 U25.16(VDD) U26.1(VCC) U29.1(VCC) U31.16(VDD) U32.16(VDD) U37.14(VCCP) U37.15(VCCI) U43.6(VS) U44.1(VDD) ; also on sheet 1 2 3 4 5 6
VDD_IO: C152.1 C161.1 C164.1 C168.1 C178.1 C186.1 C207.1 C1236.1 R120.1 R157.1 R1176.1 R1178.1 RN1.6 RN1.8 U23.16(VDD) U27.1(VL) U28.18(VL) U30.1(VL) U33.5(VIO) U34.5(VIO) U40.15(DVCC) U43.1(VDDIO) ; also on sheet 1 2 4 6
VIN: Q5.5 Q5.6 Q5.7 Q5.8 Q5.9(PAD) R155.2 R156.2 U40.3(VOUTA) U40.4(CLN) U40.27(VOUT1) U40.28(VOUT2) ; also on sheet 1
VIN_5V: J22.P2 ; also on sheet 1
VIN_BAT_CH: J22.P5 Q4.1 Q4.2 Q4.3 R155.1 U40.7(VIN) ; also on sheet 1
VIN_VIDEO: C189.1 C190.1 C1293.1 C1294.1 J24.8 J24.9 J24.10 J25.31 J25.32 J25.33 ; also on sheet 1
ALERT#: R157.2 U40.12(~{SMBALERT}) ; also on sheet 6
bDIG_IN1: C1223.1 OC2.4(COLLECTOR) R4.2 ; also on sheet 6
C_RS232A_RX: D20.2 J5004.16 U28.3(RIN1)
C_RS232A_TX: D20.1 J5004.14 U28.5(T1OUT)
C_RS232B_RX: D21.1 J5004.15 U28.4(R2IN)
C_RS232B_TX: D21.2 J5004.13 U28.6(T2OUT)
CAM_CLK: J23.15 R1221.2 TP25.1(TP)
CAM_GPIO1: J23.9 TP26.1(TP)
CAM_GPIO2: J23.11 TP27.1(TP)
CAM_SCL_1V8: J23.18 R121.2 U23.7(SC1)
CAM_SDA_1V8: J23.17 R122.2 U23.6(SD1)
CAM_TRIG: J23.19 U48.10(IO0_7)
CAM_XHS: R1222.1 ; also on sheet 6
CAM_XVS: R1217.1 R1218.1 ; also on sheet 6
CAMERA_RST_N: J23.16 R1219.2 R1220.1 U48.2(IO0_0)
CAN1_RX: U32.5(S2A) U33.4(RXD)
CAN1_TX: U32.2(S1A) U33.1(TXD)
CAN1H: C179.1 D22.2 J5004.4 J5015.1 U33.7(CANH)
CAN1L: C180.1 D22.1 J5004.2 J5014.1 U33.6(CANL)
CAN2_RX: U32.14(S4A) U34.4(RXD)
CAN2_TX: U32.11(S3A) U34.1(TXD)
CAN2H: C182.1 D23.1 J5004.1 J5017.1 U34.7(CANH)
CAN2L: C183.1 D23.2 J5004.3 J5016.1 U34.6(CANL)
CANA_RX: U31.5(S2A) ; also on sheet 6
CANA_TX: U31.2(S1A) ; also on sheet 6
CANB_RX: U31.14(S4A) ; also on sheet 6
CANB_TX: U31.11(S3A) ; also on sheet 6
CANC_RX: U31.6(S2B) ; also on sheet 6
CANC_TX: U31.3(S1B) ; also on sheet 6
CAND_RX: U31.13(S4B) ; also on sheet 6
CAND_TX: U31.10(S3B) ; also on sheet 6
COM_PWR_IN: D29.1 J5004.19 RE2.3(LOAD2)
CSELL0: J42.4 R782.1 U40.17(CSELL0)
CSELL1: J42.3 R783.1 U40.18(CSELL1)
CSI_P1_CKN: J23.24 ; also on sheet 6
CSI_P1_CKP: J23.25 ; also on sheet 6
CSI_P1_DN0: J23.22 ; also on sheet 6
CSI_P1_DN1: J23.27 ; also on sheet 6
CSI_P1_DN2: J23.20 ; also on sheet 6
CSI_P1_DN3: J23.29 ; also on sheet 6
CSI_P1_DP0: J23.23 ; also on sheet 6
CSI_P1_DP1: J23.28 ; also on sheet 6
CSI_P1_DP2: J23.21 ; also on sheet 6
CSI_P1_DP3: J23.30 ; also on sheet 6
DIG_IN1: D30.2(Cathod) J5004.18 R5.1
DIG_OUT1: R1156.1 ; also on sheet 6
DSI_CKN: J25.17 ; also on sheet 6
DSI_CKP: J25.18 ; also on sheet 6
DSI_CTP_/RST: J25.37 U48.9(IO0_6)
DSI_DN0: J25.8 ; also on sheet 6
DSI_DN1: J25.11 ; also on sheet 6
DSI_DN2: J25.14 ; also on sheet 6
DSI_DN3: J25.20 ; also on sheet 6
DSI_DP0: J25.9 ; also on sheet 6
DSI_DP1: J25.12 ; also on sheet 6
DSI_DP2: J25.15 ; also on sheet 6
DSI_DP3: J25.21 ; also on sheet 6
DSI_L/R: J25.28 U48.7(IO0_4)
DSI_PWM_BL: J25.27 U48.5(IO0_3)
DSI_RESET: J25.5 R1215.1 U48.3(IO0_1)
DSI_SCL: J25.35 R147.1 U23.10(SC2) U48.12(SCL)
DSI_SDA: J25.36 R148.1 U23.9(SD2) U48.13(SDA)
DSI_STBYB: J25.6 U48.4(IO0_2)
DSI_U/D: J25.29 U48.8(IO0_5)
EGND: C181.2 C184.2 D18.3 D19.3 D20.3 D21.3 D22.3 D23.3 D30.1(Anode) J5004.5 J5004.6 J5004.11 J5004.12 J5004.20 OC2.2(CATHODE) R124.2
EXT_CAN1_RX: J22.2 U32.6(S2B)
EXT_CAN1_TX: J22.1 U32.3(S1B)
EXT_CAN2_RX: J22.42 U32.13(S4B)
EXT_CAN2_TX: J22.41 U32.10(S3B)
EXT_MISO: J22.9 ; also on sheet 6
EXT_MOSI: J22.10 ; also on sheet 6
EXT_SCL: J22.50 R117.1 U23.5(SC0)
EXT_SCLK: J22.11 ; also on sheet 6
EXT_SDA: J22.49 R118.1 U23.4(SD0)
EXT_SS0: J22.19 ; also on sheet 6
EXT_UARTA_RX: J22.4 U25.6(S2B)
EXT_UARTA_TX: J22.5 U25.3(S1B)
EXT_UARTB_RX: J22.45 U25.13(S4B)
EXT_UARTB_TX: J22.44 U25.10(S3B)
GPIO0_1: J22.58 ; also on sheet 6
GPIO0_2: J22.65 ; also on sheet 6
GPIO0_4: J22.30 ; also on sheet 6
GPIO0_5: J22.29 ; also on sheet 6
GPIO0_6: J22.28 ; also on sheet 6
GPIO0_7: J22.8 ; also on sheet 6
GPIO0_8: J22.12 ; also on sheet 6
GPIO0_9: J22.16 ; also on sheet 6
GPIO0_10: J22.7 ; also on sheet 6
GPIO0_11: J22.13 ; also on sheet 6
GPIO0_12: J22.47 ; also on sheet 6
GPIO0_13: J22.60 ; also on sheet 6
GPIO0_14: J22.17 ; also on sheet 6
GPIO0_15: J22.25 ; also on sheet 6
GPIO0_16: J22.27 ; also on sheet 6
GPIO0_17: J22.61 ; also on sheet 6
GPIO1_0: J22.18 ; also on sheet 6
GPIO1_1: J22.63 ; also on sheet 6
GPIO1_2: J22.14 ; also on sheet 6
GPIO1_3: J22.15 ; also on sheet 6
GPIO1_4: J22.43 ; also on sheet 6
GPIO1_5: J22.48 ; also on sheet 6
GPIO1_6: J22.31 ; also on sheet 6
GPIO1_7: J22.22 ; also on sheet 6
GPIO1_8: J22.64 ; also on sheet 6
GPIO1_9: J22.62 ; also on sheet 6
GPIO1_10: J22.55 ; also on sheet 6
GPIO1_11: J22.53 ; also on sheet 6
GPIO1_12: J22.54 ; also on sheet 6
GPIO1_13: J22.56 ; also on sheet 6
GPIO1_14: J22.57 ; also on sheet 6
GPIO1_15: J22.21 ; also on sheet 6
GPIO1_16: J22.26 ; also on sheet 6
GPIO1_17: J22.23 ; also on sheet 6
GPIO1_18: J22.59 ; also on sheet 6
GPIO1_19: J22.20 ; also on sheet 6
I2C2_SCL: U23.14(SCL) ; also on sheet 3 6
I2C2_SDA: U23.15(SDA) ; also on sheet 3 6
I2C3_SCL: J22.51 U40.13(SCL) U43.14(SCL) U44.5(SCL) ; also on sheet 2 4 6
I2C3_SDA: J22.52 U40.14(SDA) U43.13(SDA) U44.6(SDA) ; also on sheet 2 4 6
I2C/SPI#: RN1.3 U43.7(CS)
I2C_A0: RN1.4 U43.12(SDO/SA0)
I2C_RST: R120.2 U23.3(RESET#) ; also on sheet 6
INT2: R1168.2 U43.9(INT2)
INT/EXT_CAN: R141.1 U32.1(SEL) ; also on sheet 6
INT/EXT_UART: R125.1 U25.1(SEL) ; also on sheet 6
INTVCC: C211.1 J42.5 J42.6 U40.2(INTVCC)
LCD_I2C_RST: U37.1(RESET#) U48.1(RESET#) ; also on sheet 6
LVDS8_CKN: J24.24 ; also on sheet 6
LVDS8_CKP: J24.23 ; also on sheet 6
LVDS8_DN0: J24.33 ; also on sheet 6
LVDS8_DN1: J24.30 ; also on sheet 6
LVDS8_DN2: J24.27 ; also on sheet 6
LVDS8_DN3: J24.21 ; also on sheet 6
LVDS8_DP0: J24.32 ; also on sheet 6
LVDS8_DP1: J24.29 ; also on sheet 6
LVDS8_DP2: J24.26 ; also on sheet 6
LVDS8_DP3: J24.20 ; also on sheet 6
LVDS_CTP_/RST: J24.4 U37.9(IO0_6)
LVDS_INT#: J24.3 J25.38 ; also on sheet 6
LVDS_L/R: J24.13 U37.7(IO0_4)
LVDS_PWM_BL: J24.14 U37.5(IO0_3)
LVDS_RESET: J24.36 R1171.1 U37.3(IO0_1)
LVDS_SCL: J24.6 R149.1 U23.12(SC3) U37.12(SCL)
LVDS_SDA: J24.5 R150.1 U23.11(SD3) U37.13(SDA)
LVDS_STBYB: J24.35 U37.4(IO0_2)
LVDS_U/D: J24.12 U37.8(IO0_5)
NXP/REN: R138.1 U31.1(SEL) ; also on sheet 6
PWR_OUT1: D29.2 J5004.17 R1112.2
RS232_ONLINE#: R1176.2 R1177.1 U28.15(~{OnLine})
RS232_SHTD#: U28.14(~{Shutdown}) ; also on sheet 6
RS232_STAT#: R1178.2 U28.13(~{Status})
RS232A_RX: U26.5(NC1) U28.12(R1OUT)
RS232A_TX: U26.7(NC2) U28.10(T1IN)
RS232B_RX: U28.11(R2OUT) U29.5(NC1)
RS232B_TX: U28.9(T2IN) U29.7(NC2)
RS485A_A/Y: D19.1 J5004.9 J5012.1 U27.8(A/Y)
RS485A_B/Z: D19.2 J5004.7 R1226.1 U27.9(B/Z)
RS485B_A/Y: D18.1 J5004.8 J5013.1 U30.8(A/Y)
RS485B_B/Z: D18.2 J5004.10 R1227.1 U30.9(B/Z)
SELB: J24.37 U37.2(IO0_0)
SENS_INT: J5007.1 R1168.1 R1169.2 RN1.1 U43.8(INT1) ; also on sheet 6
UART1_RX: U25.5(S2A) U26.3(COM1)
UART1_TX: U25.2(S1A) U26.9(COM2)
UART2_RX: U25.14(S4A) U29.3(COM1)
UART2_TX: U25.11(S3A) U29.9(COM2)
UARTA_232/485: R128.1 U26.4(SEL1) U26.8(SEL2) ; also on sheet 6
UARTA_RTS: J22.6 R126.1 R127.1 ; also on sheet 6
UARTA_RX: U25.7(D2) ; also on sheet 6
UARTA_TX: U25.4(D1) ; also on sheet 6
UARTB_232/485: R131.1 U29.4(SEL1) U29.8(SEL2) ; also on sheet 6
UARTB_RTS: J22.46 R129.1 R130.1 ; also on sheet 6
UARTB_RX: U25.12(D4) ; also on sheet 6
UARTB_TX: U25.9(D3) ; also on sheet 6
USB_5V0: C153.1 C154.1 C162.1 C163.1 C170.1 C177.1 C185.1 J23.4 U27.10(VCC) U28.19(VCC) U30.10(VCC) U33.3(VCC) U34.3(VCC) ; also on sheet 1 3 4 6
USB_HOSTDS1_DN: J22.74 ; also on sheet 3
USB_HOSTDS1_DP: J22.73 ; also on sheet 3
USBDS1_RX_N: J22.70 ; also on sheet 3
USBDS1_RX_P: J22.71 ; also on sheet 3
USBDS1_TX_N: J22.67 ; also on sheet 3
USBDS1_TX_P: J22.68 ; also on sheet 3
N18287551: C181.1 R132.2 R133.2
N18287985: C184.1 R135.2 R137.2
N18452155: R139.1 U31.15(EN)
N18545523: U29.2(NO1) U30.2(RO)
N18545536: U29.10(NO2) U30.5(DI)
N18546389: U26.2(NO1) U27.2(RO)
N18546399: U26.10(NO2) U27.5(DI)
N18553883: C165.1 U28.16(C1-)
N18553887: C165.2 U28.21(C1+)
N18553933: C169.1 U28.20(V+)
N18553975: C167.1 U28.23(C2-)
N18553979: C167.2 U28.22(C2+)
N18553981: C166.1 U28.24(V-)
N18555504: R126.2 U27.4(~{RE})
N18555511: R127.2 U27.3(DE)
N18555917: R129.2 U30.4(~{RE})
N18555941: R130.2 U30.3(DE)
N18714338: R140.1 U32.15(EN)
N18715024: U31.4(D1) U32.4(D1)
N18715027: U31.7(D2) U32.7(D2)
N18715030: U31.9(D3) U32.9(D3)
N18715033: U31.12(D4) U32.12(D4)
N18716761: R123.1 U25.15(EN)
N18902308: R134.2 U33.8(S)
N18903686: R136.2 U34.8(S)
N19283340: Q4.5 Q4.6 Q4.7 Q4.8 Q4.9(PAD) R156.1 U40.5(CLP)
N19283509: Q4.4 U40.6(INFET)
N19283852: Q5.4 U40.22(BATFET)
N19283867: C208.1 U40.1(BOOST)
N19283869: L13.2 Q5.1 Q5.2 Q5.3 R158.1 U40.21(CSP)
N19283921: C208.2 L13.1 U40.25(SW1) U40.26(SW2)
N19284042: R159.1 U40.9(NTCBIAS)
N19284044: J5006.2 R159.2 U40.10(NTC)
N19284074: R160.1 U40.11(RT)
N19284211: F3.2 J5006.1
N19292672: R1156.2 RE2.1(ANODE2)
N19292674: R1112.1 RE2.4(LOAD1)
N19306315: OC2.1(ANODE) R5.2
N19401753: R1170.1 U44.3(REXT)
N19401757: R1169.1 U44.4(~{INT})
N20081182: J23.10 R1217.2
N20081250: J23.13 R1218.2
N20081844: OSC3.3(OUT) R1221.1
N20097068: J23.12 R1222.2
N20134494: J5012.2 R1226.2
N20134593: J5013.2 R1227.2
N20134714: J5014.2 R132.1
N20134770: J5015.2 R133.1
N20135219: J5016.2 R135.1
N20135312: J5017.2 R137.1

Not connected (* = marked no-connect by the designer): J22 3 24 32 33 34 36 37 39 40 66 76 77 79 80; J23 5 6 7 8 14; J24 7 11 15 40; J25 1 4 26 30 34 39 40; RN1 2 7; U27 7(NC); U28 1(NC1) 2(NC2) 7(NC7) 8(NC8); U30 7(NC); U37 10(IO0_7) 11(\\~{INT})*; U43 3(RES2) 10(NC) 11(RES); U48 11(\\~{INT})*

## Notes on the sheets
sheet 7
- CAN_TX
- CAN_TX
- NC
- ECAT
- $0.7
- CAN_RX
- CAN_RX
- NC
- 485A_RX
- 485A_RX
- 485B_TX
- 485B_TX
- 485A_TX
- 485A_TX
- 485B_RX
- 485B_RX
- 485A_CTS
- 485A_RTS
- 485A_CTS
- 485A_RTS
- 485B_CTS
- 485B_RTS
- 485B_CTS
- 485B_RTS
- CAN_AUXIN
- CAN_AUXIN
- BT_RST
- IPMASH
- BT_PWR
- IPMASH
- BT_WAKE
- IPMASH
- BT_SDIO
- IPMASH
- BT_SDCLK
- ECAT
- 485A_INVR
- 485A_INVR
- SDIO_RST
- SDIO_RST
- 485B_INVR
- NC
- 485B_INVR
- NC
- IO_INT
- NC
- ECAT
- NC
- CAN_SILENT
- CAN_SILENT
- NC
- ECAT
- CAN_STBY
- CAN_STBY
- BT_CTS
- IPMASH
- 0b1110000
- 485A_INVD
- 485A_INVD
- NC
- ECAT
- 485B_INVD
- 485B_INVD
- BT_RTS
- IPMASH
- ECAT
- ECAT
- IO_RST
- NC
- BT_TX
- SDIO_LADC#
- IPMASH
- SDIO_LADC#
- ECAT
- NC
- BT_RX
- IPMASH
- SDIO_PWRGD
- SDIO_PWRGD
- SDIO_ALERT
- SDIO_ALERT
- SDIO_ADC
- SDIO_ADC
- $0.4
- Add: 0b0011010
       0b0010000
       0b0110110
       0b0110111
- $0.4
- b0100000
- Chane to DSI
- b0100001
- TOP
- BOT
- Check pin 1 position
- Check pin 1 position
- Add pull Up/Down
- Add pull Up/Down
sheet 8
- Accelerometer
- Ambient Light Sensor
- H-Min = 1.7V
sheet 9
- ICHARGE = (ch arge _
  current _ setting + 1)
  x 1mV/RSNSB
  ch arge _ current _
  setting = 31
- 2A
- 0b1101000
- Two cells battery connector
- NTC
sheet 10
- Rev. 1.0
- Prototype Version
- Rev. 1.1
- 1. Fix Ethernet lines going vis the TVS diodes.
- 2. Fix USB power rail. Connecting 5V to the USB power.
- 3. Fix the TVS diode, D5, Cathode marking
- 4. Swap the DSI and LVDS connector's pin numbering
- 5. Move J15, J16 and J17 to bottom
- 6. Move J18, J19, J20 and J21 to bottom
- 7. Change U48-12 to DSI_SCL and U48-13 to DSI_SDA
- 8. VCCI and VCCP are switched in U20 and U21. Changing the symbol to correct it. (Pins 21 and 23 are swapped)
- 9. M.2 Key-B - changing R60 from 100K to 10K and not assembling some of the PU/PD.
- 10. Changing the M.2 spacers, J5 and J14, height to 1.5 m"m (MCH0008).
- 11. Changing U23 to TCA9546APWR to support 1.8V VCC
- 12. Adding PU resistor, R1216 and R1230, on SPI_CS as anassembly option.
- 13. Changing the Camera connectro, J23, to support Leopard's Camera.
- 14. Adding PD resistors on CC1 and CC2 (Type-C) to support connection to Type-C DFP.
- 15. Adding termination resistors on RS-485 and jumpers.
- 16. Adding jumpers to the CAN termination.
- 17. Adding GND test points.
- 18. Adding two power leds, VDDIO and VIN_SOM_5V.
- 19. Changed the routing of Mode0 and Mode1 in S5.
sheet 11
- $0.2
- $0.15
- $1.15
- 1.65 V to 3.6 V
- 0.8V
- 0.8V
- $1
- Digital In
- $0.15
- $1.15
- 1.65 V to 3.6 V
- 0.8V
- 0.8V
- Digital Out
- TYP. 1.22V, 3ma
- $0.2
- $0.2
